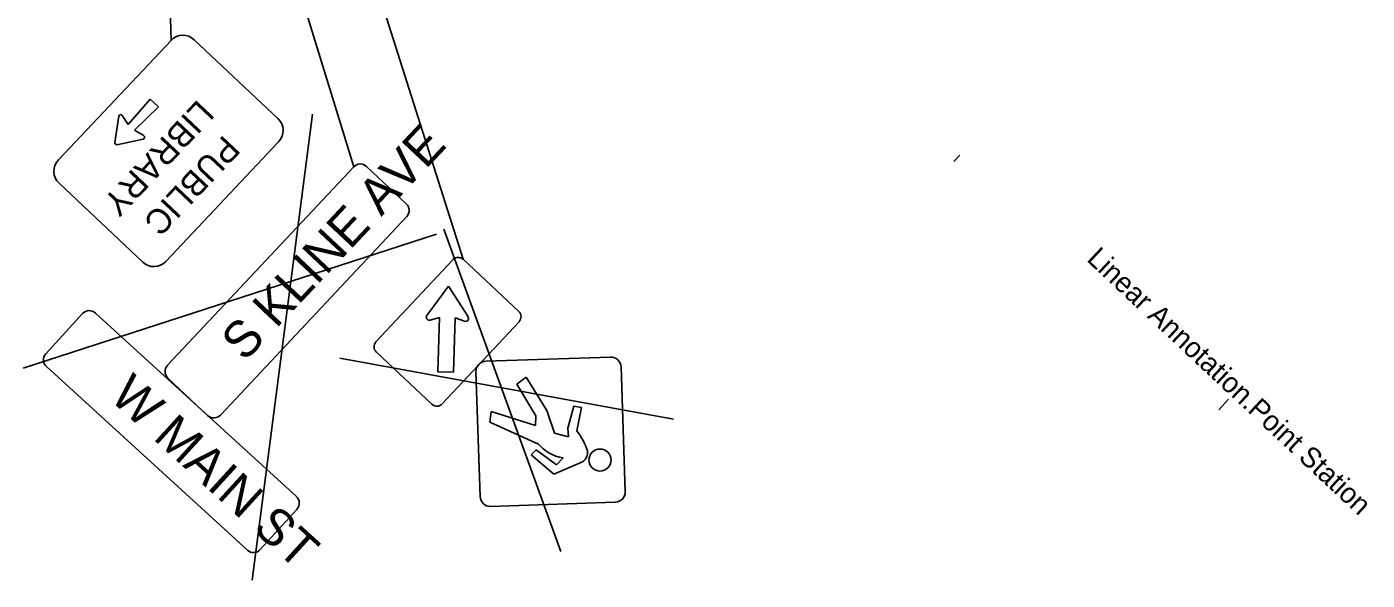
# Model space of a CAD drawing. Extents: x 1470334 to 1481646, y 379063 to 388330.
# Drawn here: x 1480147.4 to 1480332.2, y 379268.5 to 379344.8 of the extents above; entities that cross this region are included whole.
import ezdxf

# ---------------------------------------------------------------- set-up
doc = ezdxf.new("R2010")
doc.units = 0
for name, color, linetype in [('Default', 7, 'Continuous'), ('SV_X_Text_Description', 7, 'Continuous'), ('UT_X_Electric_Cells', 7, 'Continuous')]:
    doc.layers.add(name, color=color, linetype=linetype)

msp = doc.modelspace()

# ---------------------------------------------------------------- linework, layer by layer
at = {"layer": 'Default'}
for p, q in [((1480275.2, 379326.2), (1480276.02, 379327.07)), ((1480275.2, 379326.2), (1480276.02, 379327.07)), ((1480311.7, 379292.03), (1480313.06, 379293.49)), ((1480311.7, 379292.03), (1480313.06, 379293.49))]:
    msp.add_line(p, q, dxfattribs=at)
at = {"layer": 'SV_X_Text_Description'}
for p, q in [((1480192.5, 379325.47), (1480175.7, 379380.22)), ((1480167.32, 379342.89), (1480166.17, 379379.71)), ((1480207.56, 379312.74), (1480189.56, 379369.41)), ((1480164.45, 379334.81), (1480161.43, 379331.33)), ((1480164.45, 379334.81), (1480161.43, 379331.33)), ((1480162.28, 379330.52), (1480165.58, 379333.74)), ((1480162.28, 379330.52), (1480165.58, 379333.74)), ((1480165.58, 379333.74), (1480164.45, 379334.81)), ((1480165.58, 379333.74), (1480164.45, 379334.81)), ((1480160.14, 379332.46), (1480159.58, 379328.81)), ((1480160.14, 379332.46), (1480159.58, 379328.81)), ((1480161.43, 379331.33), (1480160.6, 379332.56)), ((1480161.43, 379331.33), (1480160.6, 379332.56)), ((1480163.56, 379329.77), (1480162.28, 379330.52)), ((1480163.56, 379329.77), (1480162.28, 379330.52)), ((1480162.58, 379331.81), (1480162.58, 379331.81)), ((1480159.87, 379328.53), (1480163.48, 379329.31)), ((1480159.87, 379328.53), (1480163.48, 379329.31)), ((1480195.56, 379301.37), (1480206.15, 379312.69)), ((1480207.56, 379312.74), (1480215.23, 379305.56)), ((1480202.57, 379305.02), (1480205.54, 379309.06)), ((1480205.54, 379309.06), (1480208.2, 379304.9)), ((1480202.57, 379305.02), (1480202.57, 379305.02)), ((1480204.31, 379304.73), (1480203.01, 379304.37)), ((1480204.07, 379297.26), (1480204.31, 379304.73)), ((1480215.28, 379304.15), (1480204.69, 379292.83)), ((1480206.49, 379304.66), (1480206.25, 379297.19)), ((1480207.76, 379304.22), (1480206.49, 379304.66)), ((1480203.27, 379292.78), (1480195.61, 379299.96)), ((1480206.25, 379297.19), (1480204.07, 379297.26)), ((1480214.95, 379295.54), (1480216.24, 379296.5)), ((1480217.6, 379291.16), (1480214.95, 379295.54)), ((1480216.24, 379296.5), (1480219.11, 379291.92)), ((1480211.25, 379290.32), (1480211.43, 379291.78)), ((1480211.43, 379291.78), (1480217.56, 379289.84)), ((1480219.11, 379291.92), (1480220.15, 379288.78)), ((1480222, 379289.48), (1480222.83, 379292.5)), ((1480222.83, 379292.5), (1480223.88, 379292.33)), ((1480223.88, 379292.33), (1480223.25, 379289.12)), ((1480217.96, 379287.29), (1480211.25, 379290.32)), ((1480217.56, 379289.84), (1480217.6, 379291.16)), ((1480222.1, 379288.31), (1480222, 379289.48)), ((1480220.15, 379288.78), (1480222.1, 379288.31)), ((1480216.96, 379285.79), (1480217.63, 379286.52)), ((1480220.06, 379283.16), (1480216.96, 379285.79)), ((1480217.63, 379286.52), (1480220.45, 379284.42)), ((1480224.04, 379284.86), (1480220.06, 379283.16)), ((1480220.45, 379284.42), (1480221.34, 379285.38))]:
    msp.add_line(p, q, dxfattribs=at)
for points in [[(1480170.52, 379342.99), (1480182.05, 379332.12)], [(1480151.79, 379326.43), (1480167.32, 379342.89)], [(1480182.14, 379328.92), (1480166.61, 379312.45)], [(1480192.5, 379325.47), (1480166.83, 379298.14)], [(1480194.26, 379325.53), (1480199.73, 379320.4)], [(1480163.41, 379312.36), (1480151.89, 379323.23)], [(1480174.12, 379291.29), (1480199.79, 379318.63)], [(1480155.13, 379305.26), (1480150.07, 379299.73)], [(1480184.59, 379280.06), (1480156.89, 379305.34)], [(1480210.69, 379298.7), (1480227.88, 379299.27)], [(1480150.15, 379297.96), (1480177.84, 379272.67)], [(1480209.91, 379280.06), (1480209.34, 379297.25)], [(1480229.33, 379297.91), (1480229.9, 379280.72)], [(1480166.88, 379296.37), (1480172.35, 379291.24)], [(1480184.67, 379278.29), (1480179.61, 379272.75)], [(1480228.54, 379279.28), (1480211.35, 379278.71)]]:
    msp.add_lwpolyline(points, dxfattribs=at)
msp.add_circle((1480226.43, 379285.09), 1.52, dxfattribs=at)
for centre, radius, start, end in [((1480168.97, 379341.34), 2.26, 46.6795, 136.6795), ((1480160.39, 379332.42), 0.253, 33.7033, 171.1766), ((1480160.39, 379332.42), 0.253, 33.7033, 171.1766), ((1480180.5, 379330.47), 2.26, 316.6795, 46.6795), ((1480159.83, 379328.78), 0.253, 172.5858, 280.7731), ((1480159.83, 379328.78), 0.253, 172.5858, 280.7731), ((1480163.43, 379329.55), 0.253, 282.1824, 59.6557), ((1480163.43, 379329.55), 0.253, 282.1824, 59.6557), ((1480153.44, 379324.87), 2.26, 136.6795, 226.6795), ((1480193.41, 379324.62), 1.25, 46.8, 136.8), ((1480198.88, 379319.48), 1.25, 316.8, 46.8), ((1480164.97, 379314), 2.26, 226.6795, 316.6795), ((1480206.88, 379312.01), 1, 46.9, 136.9), ((1480156.05, 379304.42), 1.25, 47.6, 137.6), ((1480202.9, 379304.77), 0.417, 143.5699, 285.3633), ((1480207.9, 379304.61), 0.417, 250.9541, 43.1683), ((1480214.55, 379304.83), 1, 316.9, 46.9), ((1480196.29, 379300.69), 1, 136.9, 226.9), ((1480150.99, 379298.88), 1.25, 137.6, 227.6), ((1480210.74, 379297.3), 1.4, 91.9, 181.9), ((1480227.93, 379297.87), 1.4, 1.9, 91.9), ((1480167.74, 379297.28), 1.25, 136.8, 226.8), ((1480173.21, 379292.15), 1.25, 226.8, 316.8), ((1480203.96, 379293.51), 1, 226.9, 316.9), ((1480215.51, 379283.3), 9.69, 18.4411, 36.9317), ((1480222.23, 379290.95), 5.64, 218.7502, 260.9609), ((1480223.22, 379286.12), 1.5, 303.1441, 9.395), ((1480228.5, 379280.68), 1.4, 271.9, 1.9), ((1480183.74, 379279.14), 1.25, 317.6, 47.6), ((1480211.31, 379280.11), 1.4, 181.9, 271.9), ((1480178.69, 379273.6), 1.25, 227.6, 317.6)]:
    msp.add_arc(centre, radius, start, end, dxfattribs=at)
at = {"layer": 'UT_X_Electric_Cells'}
for p, q in [((1480178.48, 379268.55), (1480186.83, 379332.73)), ((1480146.94, 379297.73), (1480203.91, 379316.22)), ((1480221.05, 379272.51), (1480204.9, 379316.88)), ((1480190.56, 379299.14), (1480236.58, 379290.71))]:
    msp.add_line(p, q, dxfattribs=at)

# ---------------------------------------------------------------- texts
at = {"layer": 'Default'}
msp.add_text('Linear Annotation.Point Station', height=2.8, rotation=316.886, dxfattribs=at).set_placement((1480293.37, 379312.61))
msp.add_text('Linear Annotation.Point Station', height=2.8, rotation=316.886, dxfattribs=at).set_placement((1480293.37, 379312.61))
at = {"layer": 'SV_X_Text_Description'}
for s, height, rotation, p in [('LIBRARY', 3.395, 226.6795, (1480171.04, 379334.88)), ('     S KLINE AVE', 5, 46.8, (1480171.11, 379291.74)), ('PUBLIC', 3.395, 226.6795, (1480174.61, 379330)), ('      W MAIN ST', 5, 317.6, (1480150.45, 379301.08))]:
    msp.add_text(s, height=height, rotation=rotation, dxfattribs=at).set_placement(p)

doc.saveas('drawing.dxf')
